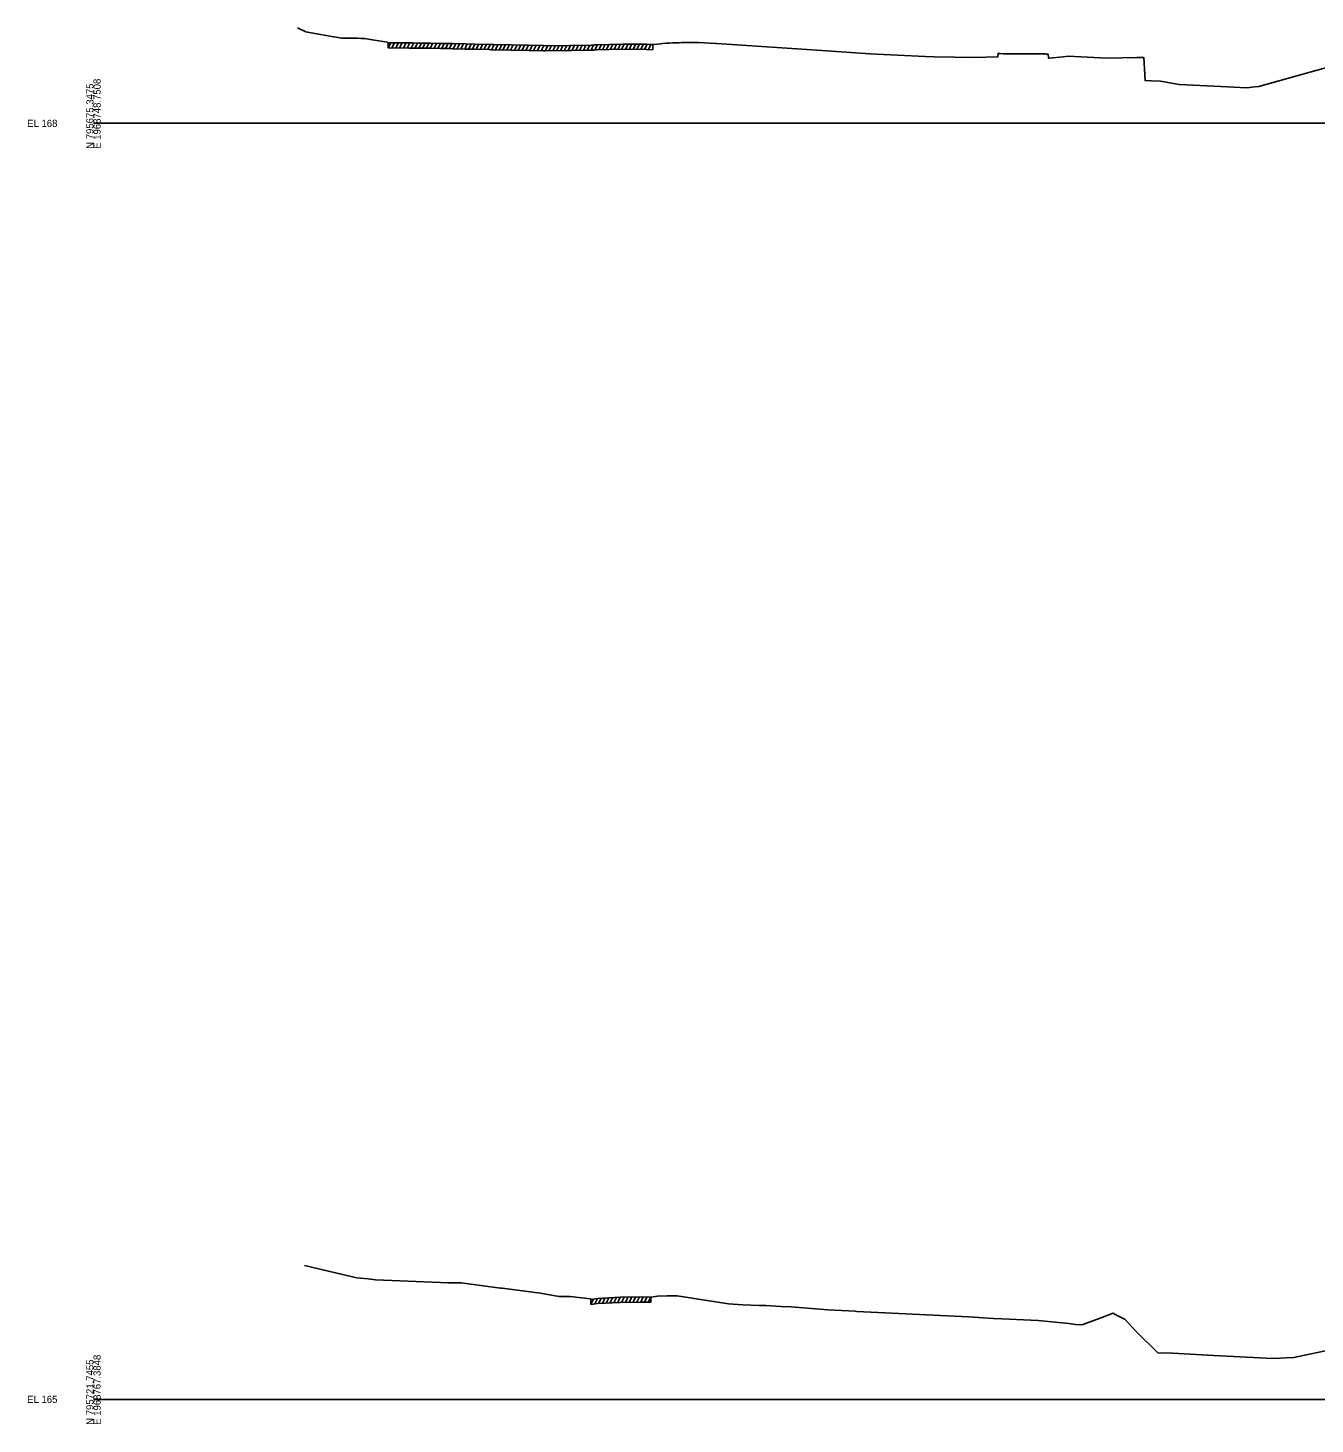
# Model space of a CAD drawing. Extents: x 1017 to 19997, y -1947 to 50737.
# Drawn here: x 15974 to 16479, y 7990 to 8537 of the extents above; entities that cross this region are included whole.
import ezdxf

# ---------------------------------------------------------------- set-up
doc = ezdxf.new("R2010")
doc.units = 0
for name, color, linetype in [('RD_GPK_XS_Cell', 7, 'Continuous'), ('RD_XS_ExGround', 7, 'Continuous'), ('RD_XS_ExPaveRet', 7, 'Continuous')]:
    doc.layers.add(name, color=color, linetype=linetype)

msp = doc.modelspace()

# ---------------------------------------------------------------- linework, layer by layer
at = {"layer": 'RD_GPK_XS_Cell'}
for p, q in [((16000, 8500), (16600, 8500)), ((16000, 8000), (16600, 8000))]:
    msp.add_line(p, q, dxfattribs=at)
at = {"layer": 'RD_XS_ExGround'}
for points in [[(16079.98, 8537.38), (16083.21, 8535.9), (16088.19, 8534.95), (16094.17, 8533.85), (16095.05, 8533.73), (16097.3, 8533.32), (16100.2, 8533.32), (16103.41, 8533.31), (16104.81, 8533.3), (16106.19, 8533.3), (16110.08, 8532.62), (16115.22, 8531.76), (16115.48, 8531.55), (16123.68, 8531.51), (16124.99, 8531.49), (16127.49, 8531.45), (16132.03, 8531.4), (16136.09, 8531.31), (16139.33, 8531.26), (16140.65, 8531.24), (16145.81, 8531.11), (16149.34, 8531.04), (16155.04, 8530.88), (16155.77, 8530.86), (16156.74, 8530.84), (16170.6, 8530.6), (16176.3, 8530.44), (16176.96, 8530.42), (16186.64, 8530.48), (16187.44, 8530.49), (16195.17, 8530.66), (16195.48, 8530.66), (16196.13, 8530.72), (16197.06, 8530.77), (16207.14, 8531.04), (16216.77, 8530.99), (16219.24, 8530.85), (16220.95, 8531.05), (16224.29, 8531.37), (16225.69, 8531.47), (16227.01, 8531.58), (16229.06, 8531.6), (16229.41, 8531.6), (16230.56, 8531.61), (16232.31, 8531.62), (16233.98, 8531.61), (16236.08, 8531.68), (16236.69, 8531.66), (16237.1, 8531.65), (16243.84, 8531.28), (16244.3, 8531.25), (16287.43, 8528.36), (16304.29, 8527.18), (16325.95, 8526.25), (16329.4, 8526.09), (16345.1, 8525.76), (16354.34, 8526.01), (16354.55, 8527.43), (16354.87, 8527.41), (16355.29, 8527.41), (16356.43, 8527.27), (16367.54, 8527.19), (16372.95, 8527.18), (16373.31, 8527.15), (16374.08, 8527.15), (16374.26, 8525.51), (16374.62, 8525.5), (16380.05, 8526.08), (16381.94, 8526.26), (16397.06, 8525.52), (16408.92, 8525.8), (16410.7, 8525.75), (16411.66, 8525.75), (16412.08, 8516.78), (16414.54, 8516.63), (16418.14, 8516.56), (16425.49, 8515.26), (16441.8, 8514.38), (16451.93, 8513.97), (16454.97, 8514.3), (16456.61, 8514.42), (16468.32, 8517.7), (16490.82, 8523.98)], [(16082.68, 8052.44), (16083.32, 8052.25), (16085.91, 8051.7), (16103.23, 8047.59), (16107.65, 8047.27), (16110.53, 8046.83), (16139.1, 8045.63), (16144.13, 8045.61), (16159.51, 8043.6), (16160.15, 8043.53), (16174.08, 8041.75), (16175.24, 8041.56), (16180.11, 8040.74), (16182.45, 8040.33), (16186.25, 8040.32), (16186.84, 8040.27), (16194.83, 8039.37), (16194.93, 8039.17), (16197.55, 8039.49), (16206.41, 8039.98), (16214.75, 8040.13), (16218.43, 8040.02), (16218.53, 8040.1), (16221.02, 8040.37), (16224.83, 8040.56), (16227.22, 8040.62), (16228.79, 8040.62), (16248.82, 8037.37), (16254.48, 8037.08), (16260.87, 8036.82), (16261.44, 8036.75), (16263.43, 8036.71), (16269.41, 8036.42), (16273.42, 8036.21), (16287.77, 8035.02), (16298.44, 8034.5), (16299.08, 8034.45), (16342.84, 8032.29), (16352.55, 8031.68), (16356, 8031.52), (16370.2, 8030.85), (16382.27, 8029.68), (16384.81, 8029.35), (16387.28, 8029.14), (16393.51, 8031.42), (16399.57, 8033.71), (16400.63, 8033.11), (16403.45, 8031.63), (16404.25, 8031.25), (16408.37, 8026.89), (16417.28, 8018.14), (16419.85, 8018.22), (16422.83, 8018.03), (16439.01, 8017.18), (16459.61, 8016.13), (16462.94, 8016.02), (16467.25, 8016.23), (16470.35, 8016.39), (16474.65, 8017.34), (16487.14, 8019.98)]]:
    msp.add_lwpolyline(points, dxfattribs=at)
at = {"layer": 'RD_XS_ExPaveRet'}
for p, q in [((16115.48, 8529.55), (16116.48, 8531.55)), ((16115.48, 8529.55), (16115.48, 8531.55)), ((16115.48, 8529.55), (16123.68, 8529.51)), ((16116.98, 8529.54), (16117.98, 8531.54)), ((16118.48, 8529.54), (16119.48, 8531.53)), ((16119.98, 8529.53), (16120.98, 8531.52)), ((16121.48, 8529.52), (16122.48, 8531.51)), ((16122.98, 8529.51), (16123.98, 8531.5)), ((16123.68, 8529.51), (16124.99, 8529.49)), ((16124.48, 8529.5), (16125.48, 8531.48)), ((16124.99, 8529.49), (16127.49, 8529.45)), ((16125.98, 8529.48), (16126.97, 8531.46)), ((16127.48, 8529.45), (16128.48, 8531.44)), ((16127.49, 8529.45), (16132.03, 8529.4)), ((16128.98, 8529.43), (16129.98, 8531.42)), ((16130.48, 8529.41), (16131.48, 8531.4)), ((16131.98, 8529.4), (16132.97, 8531.37)), ((16132.03, 8529.4), (16136.09, 8529.31)), ((16133.48, 8529.36), (16134.47, 8531.34)), ((16134.98, 8529.33), (16135.97, 8531.31)), ((16136.09, 8529.31), (16139.33, 8529.26)), ((16136.48, 8529.3), (16137.48, 8531.29)), ((16137.98, 8529.28), (16138.98, 8531.27)), ((16139.33, 8529.26), (16140.65, 8529.24)), ((16139.48, 8529.26), (16140.48, 8531.24)), ((16140.65, 8529.24), (16145.81, 8529.11)), ((16140.98, 8529.23), (16141.97, 8531.21)), ((16142.48, 8529.19), (16143.47, 8531.17)), ((16143.98, 8529.16), (16144.97, 8531.13)), ((16145.48, 8529.12), (16146.47, 8531.1)), ((16145.81, 8529.11), (16149.34, 8529.04)), ((16146.98, 8529.09), (16147.97, 8531.07)), ((16148.48, 8529.06), (16149.47, 8531.03)), ((16149.34, 8529.04), (16155.04, 8528.88)), ((16149.98, 8529.02), (16150.97, 8530.99)), ((16151.48, 8528.98), (16152.47, 8530.95)), ((16152.98, 8528.94), (16153.97, 8530.91)), ((16154.48, 8528.9), (16155.47, 8530.87)), ((16155.98, 8528.86), (16156.97, 8530.83)), ((16157.48, 8528.83), (16158.47, 8530.81)), ((16158.98, 8528.8), (16159.97, 8530.78)), ((16160.48, 8528.77), (16161.47, 8530.76)), ((16161.98, 8528.75), (16162.97, 8530.73)), ((16163.48, 8528.72), (16164.47, 8530.7)), ((16164.98, 8528.7), (16165.97, 8530.68)), ((16166.48, 8528.67), (16167.47, 8530.65)), ((16167.98, 8528.64), (16168.97, 8530.63)), ((16169.48, 8528.62), (16170.47, 8530.6)), ((16170.98, 8528.59), (16171.97, 8530.56)), ((16172.48, 8528.55), (16173.47, 8530.52)), ((16173.98, 8528.51), (16174.97, 8530.48)), ((16175.48, 8528.46), (16176.47, 8530.44)), ((16176.98, 8528.42), (16177.99, 8530.43)), ((16178.48, 8528.43), (16179.49, 8530.44)), ((16179.98, 8528.44), (16180.99, 8530.45)), ((16181.48, 8528.45), (16182.49, 8530.46)), ((16182.98, 8528.46), (16183.99, 8530.47)), ((16184.48, 8528.47), (16185.49, 8530.47)), ((16185.98, 8528.48), (16186.99, 8530.48)), ((16187.48, 8528.49), (16188.49, 8530.51)), ((16188.98, 8528.52), (16189.99, 8530.54)), ((16190.48, 8528.55), (16191.49, 8530.58)), ((16191.98, 8528.59), (16192.99, 8530.61)), ((16193.48, 8528.62), (16194.49, 8530.64)), ((16194.98, 8528.65), (16196.01, 8530.71)), ((16196.48, 8528.74), (16197.5, 8530.78)), ((16197.06, 8528.77), (16207.14, 8529.04)), ((16197.98, 8528.8), (16199, 8530.82)), ((16199.48, 8528.84), (16200.5, 8530.86)), ((16200.98, 8528.88), (16202, 8530.9)), ((16202.48, 8528.91), (16203.5, 8530.94)), ((16203.98, 8528.95), (16205, 8530.98)), ((16205.48, 8528.99), (16206.5, 8531.02)), ((16206.98, 8529.03), (16207.98, 8531.03)), ((16207.14, 8529.04), (16216.77, 8528.99)), ((16208.48, 8529.03), (16209.48, 8531.03)), ((16209.98, 8529.02), (16210.98, 8531.02)), ((16211.48, 8529.02), (16212.48, 8531.01)), ((16212.98, 8529.01), (16213.98, 8531)), ((16214.48, 8529), (16215.48, 8531)), ((16215.98, 8529), (16216.98, 8530.98)), ((16216.77, 8528.99), (16219.24, 8528.85)), ((16217.48, 8528.95), (16218.46, 8530.9)), ((16219.24, 8530.85), (16219.24, 8528.85)), ((16155.04, 8528.88), (16155.77, 8528.86)), ((16155.77, 8528.86), (16156.74, 8528.84)), ((16156.74, 8528.84), (16170.6, 8528.6)), ((16170.6, 8528.6), (16176.3, 8528.44)), ((16176.3, 8528.44), (16176.96, 8528.42)), ((16176.96, 8528.42), (16186.64, 8528.48)), ((16186.64, 8528.48), (16187.44, 8528.49)), ((16187.44, 8528.49), (16195.17, 8528.66)), ((16195.17, 8528.66), (16195.48, 8528.66)), ((16195.48, 8528.66), (16196.13, 8528.72)), ((16196.13, 8528.72), (16197.06, 8528.77)), ((16194.93, 8037.17), (16195.99, 8039.3)), ((16194.93, 8037.17), (16194.93, 8039.17)), ((16194.93, 8037.17), (16197.55, 8037.49)), ((16196.43, 8037.36), (16197.49, 8039.49)), ((16197.55, 8037.49), (16206.41, 8037.98)), ((16197.93, 8037.51), (16198.95, 8039.57)), ((16199.43, 8037.6), (16200.45, 8039.65)), ((16200.93, 8037.68), (16201.95, 8039.73)), ((16202.43, 8037.76), (16203.45, 8039.82)), ((16203.93, 8037.84), (16204.95, 8039.9)), ((16205.43, 8037.92), (16206.45, 8039.98)), ((16206.41, 8037.98), (16214.75, 8038.13)), ((16206.93, 8037.99), (16207.93, 8040.01)), ((16208.43, 8038.01), (16209.43, 8040.03)), ((16209.93, 8038.04), (16210.93, 8040.06)), ((16211.43, 8038.07), (16212.43, 8040.09)), ((16212.93, 8038.1), (16213.93, 8040.11)), ((16214.43, 8038.12), (16215.42, 8040.11)), ((16214.75, 8038.13), (16218.43, 8038.02)), ((16215.93, 8038.09), (16216.91, 8040.07)), ((16217.43, 8038.05), (16218.41, 8040.02)), ((16218.43, 8040.02), (16218.43, 8038.02))]:
    msp.add_line(p, q, dxfattribs=at)

# ---------------------------------------------------------------- texts
at = {"layer": 'RD_GPK_XS_Cell'}
for s, p in [('N 795675.3475', (16000, 8490)), ('E 1968748.7508', (16002.8, 8490)), ('N 795721.7455', (16000, 7990)), ('E 1968767.3848', (16002.8, 7990))]:
    msp.add_text(s, height=2.8, rotation=90, dxfattribs=at).set_placement(p)
for s, p in [('EL 168', (15974, 8498.6)), ('EL 165', (15974, 7998.6))]:
    msp.add_text(s, height=2.8, dxfattribs=at).set_placement(p)

doc.saveas('drawing.dxf')
